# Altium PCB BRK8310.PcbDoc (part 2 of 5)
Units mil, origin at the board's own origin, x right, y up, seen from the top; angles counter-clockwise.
Board outline 6600.39 x 4492.13 mil, 4 copper layers (L1-Top, L2-GND, L3-GND, L4-BOT), stack 60.25 mil thick; 119 components, 266 nets, 1026 pads, 596 vias.
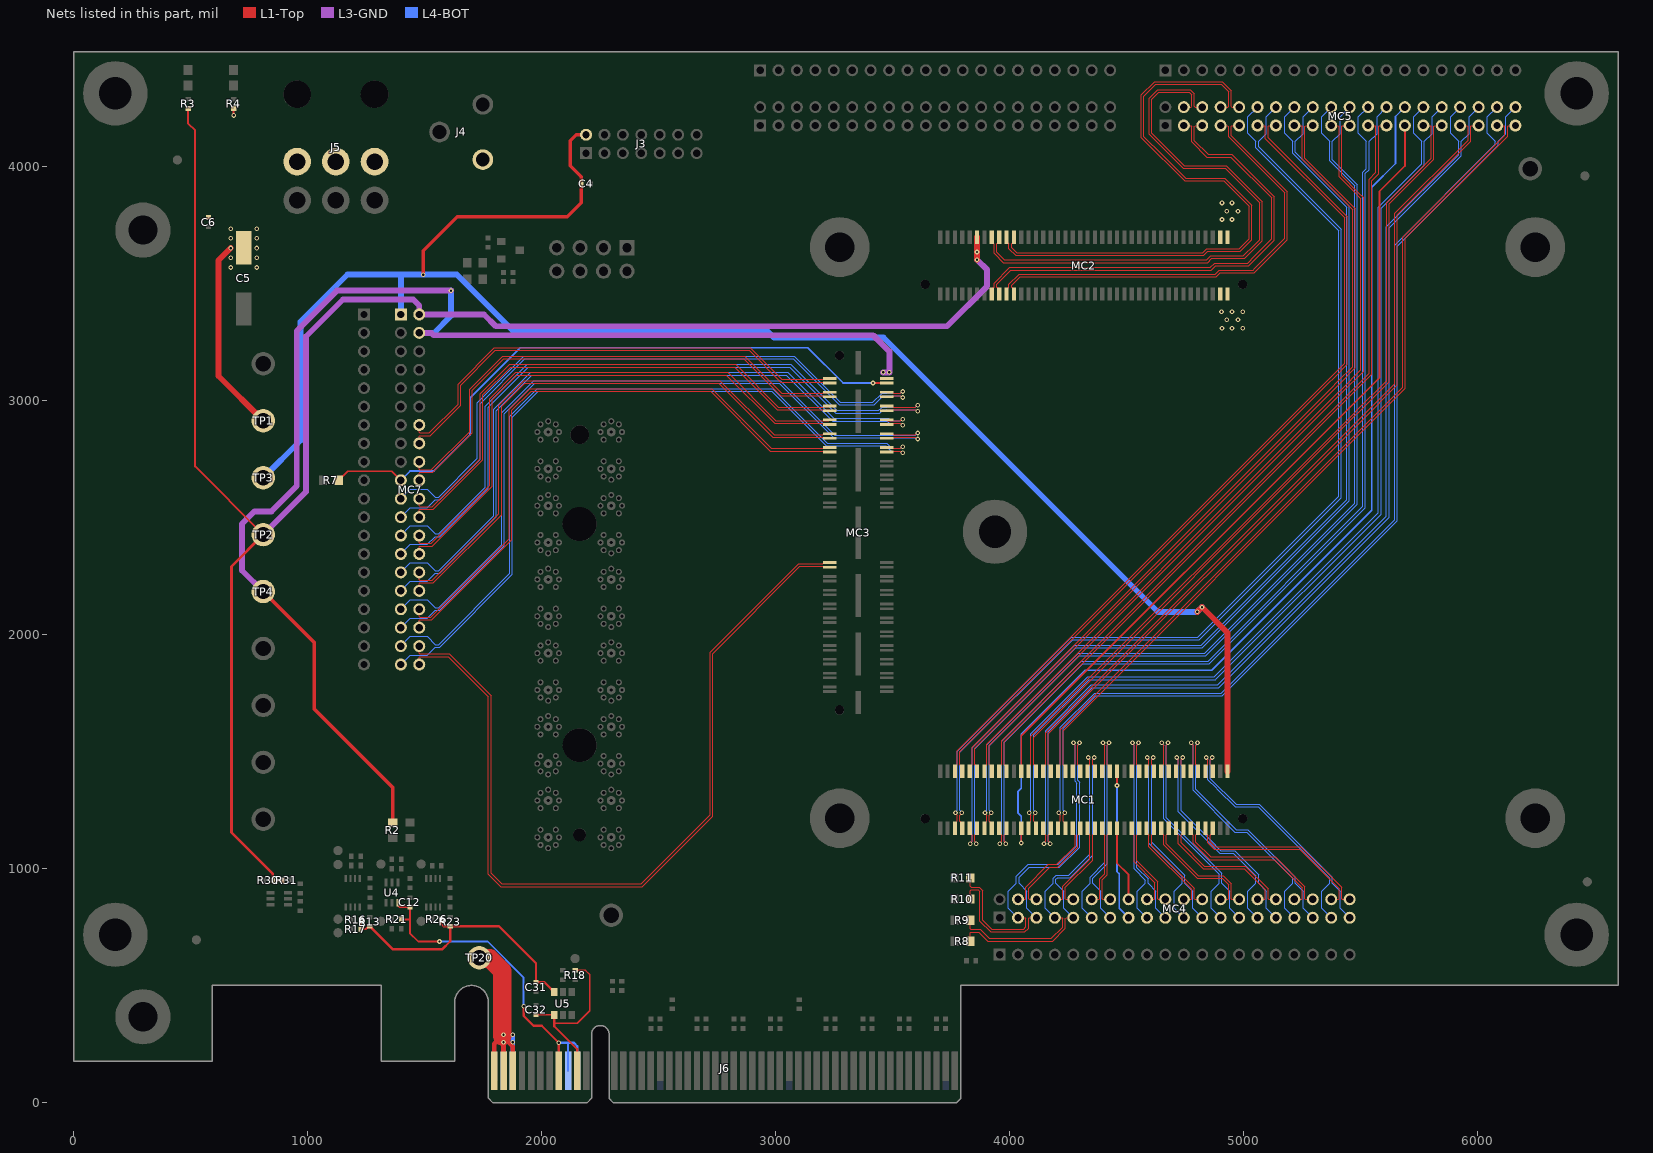
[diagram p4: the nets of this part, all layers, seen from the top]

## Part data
*: library part OKLOGO, partnumber=ALIGNI_IGNORE
C1 C3 C4: library part 000070, "Ceramic capacitor", Manufacturer=Kemet, Tolerance (%)=10, ValueFloat=1E-7
C2: library part 001983, "Ceramic capacitor", Manufacturer=Murata, Tolerance (%)=20, ValueFloat=1E-5
C5: library part 001532, "Polarized", Manufacturer=Panasonic, ValueFloat=0.00022, Voltage=25V, x_tolerance=20, x_voltage-rating=25
C6: library part 001073, "Ceramic capacitor", Manufacturer="Taiyo Yuden", Tolerance (%)=10, ValueFloat=1E-7, Voltage=25V
C7 C8 C9 C10 C11 C12 C13 C14 C15 C16 C17 C18 C19 C20 C21 C22 C23 C24 C25 C26 C27 C28 C29 C30 C31 C32: library part 001073, Manufacturer=Kemet, partnumber=000070, ValueFloat=1E-7, x_tolerance=10
D1 D2: library part 001433, "LED", Manufacturer=Dialight, Manufacturer_PN=598-8070-107F
FID1 FID2 FID3 FID4: "PCB fiducial"
J1: Package=None
J2: library part 001193, Manufacturer="Sullins Electronics Corp."
J3: library part 000541, "2mm header, shrouded", Manufacturer=Molex
J4: library part 000356, "DC power connector - high current", Manufacturer="CUI Inc."
J5: library part 001950, Manufacturer=Molex
J6: library part PCIEX8
MC1 MC2: library part 000059, "0.8mm high-density header", Manufacturer=Samtec
MC3: library part 002313, "0.5mm hi-speed, high-density header (female)", Manufacturer=Samtec
MC4 MC5 MC6 MC7: library part 000583, Manufacturer=Molex
MC8 MC9 MC10 MC11: library part 001334, Manufacturer=3M, Manufacturer_PN=951120-8622-AR
MH1 MH2 MH3 MH4: "Mounting hole"
Q1: library part 002018, Manufacturer=Vishay
R1 R2 R5 R6 R7 R8 R9 R10 R11: library part 000411, "Zero-ohm resistor", Manufacturer=Vishay, ValueFloat=0
R3: library part 001038, "Thick-film resistor", Manufacturer=Vishay, Tolerance (%)=1, ValueFloat=549
R4: library part 001162, "Thick-film resistor", Manufacturer=Vishay, Tolerance (%)=1, ValueFloat=2000
R12 R16 R17 R20 R21 R22 R26: library part Resistor-NoLoad, "Resistor, NoLoad", partnumber=ALIGNI_IGNORE
R13 R23: library part 000964, Manufacturer=Vishay, ValueFloat=200000, x_tolerance=1
R14 R15 R30 R31: library part 001008, Manufacturer=Vishay, ValueFloat=4750, x_tolerance=1
R18 R24 R25 R32 R33: library part 001070, "Thick-film resistor", Manufacturer=Vishay, Tolerance (%)=1, ValueFloat=100000
R27 R28 R29: library part 000755, Manufacturer=Vishay, ValueFloat=0, x_tolerance=1
TP1 TP2 TP3 TP4 TP5 TP6 TP7 TP8 TP17 TP18 TP19 TP20: library part TP-PTH-65/100, "Test point, plated through-hole, 65/100mil"
TP9 TP10 TP11 TP12 TP13 TP14 TP15 TP16 TP21: library part TESTPOINT-SMD40, "Test point, surface-mount, 40mil"
U1: library part 000728, "1.25V Voltage Reference", Manufacturer="Texas Instruments"
U2 U6: library part 001474, Manufacturer="Texas Instruments"
U4: library part 002140, "Level Translator, 0.65V - 3.6V, Direction Control", Manufacturer="Texas Instruments"
U5: library part 002224, "Load Switch with Adjustable Current Limit, Latching", Manufacturer="Diodes Incorporated"

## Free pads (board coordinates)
  round 236.22 hole 125.2: 0(295.27,368.11) 0(295.27,3730.31)
  round 275.59 hole 137.8: MH(177.17,718.5) MH(177.17,4314.96) MH(3937.01,2440.94) MH(6423.22,718.5) MH(6423.23,4314.96)

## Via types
v1: diameter 20, hole 10, L1-Top to L4-BOT, tented both sides, 596 vias

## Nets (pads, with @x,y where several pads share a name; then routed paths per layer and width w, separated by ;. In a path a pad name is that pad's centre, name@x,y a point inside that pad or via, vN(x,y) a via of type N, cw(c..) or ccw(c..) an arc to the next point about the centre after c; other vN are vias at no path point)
+1.2V_DDR: MC3.80 MC7.4 R2.2 TP4.1 | length 5669
  L1-Top w16: TP4.1@809.29,2185.43 1027.56,1967.16 1027.56,1683.59 1363.39,1347.76 R2.2@1363.39,1198.78
  L3-GND w25: TP4.1@809.29,2185.43 718.88,2275.84 718.88,2474.79 772.22,2528.12 844.46,2528.12 952.76,2636.42 952.76,3299.21 1125.12,3471.58 v1(1612.15,3471.58) ; MC7.4@1476.37,3290.86 1527.89,3290.86 1538.03,3280.72 3416.06,3280.72 3485.62,3211.17 v1(3485.62,3122.05) v1(3458.93,3122.05)
  L4-BOT w25: MC7.4@1476.37,3290.86 1538.89,3290.86 1612.15,3364.12 v1(1612.15,3471.58)
+1.8V: C4.1 J3.2 MC1.2 MC7.1 TP3.1 | length 7445.3
  L1-Top w15: v1(1493.22,3540.1) 1493.22,3641.64 1638.98,3787.4 2108.54,3787.4 2169.04,3847.9 C4.1@2169.04,3927.72 2169.04,3958.48 2122.05,4005.47 2122.05,4111.84 2148,4137.79 J3.2@2189.12,4137.79
  L1-Top w25: v1(4801.52,2098.74) v1(4821.74,2118.94) ; v1(4821.74,2118.94) 4931.09,2009.59 MC1.2@4931.09,1416.73
  L4-BOT w25: TP3.1@809.29,2672.2 968.5,2831.41 968.5,3338.58 1170.02,3540.1 1397.63,3540.1 ; MC7.1@1397.63,3369.6 1397.63,3540.1 ; v1@4821.73,2118.95 v1(4801.52,2098.74) 4801.18,2098.4 4633.88,2098.4 3460.62,3271.65 2991.73,3271.65 2960.23,3303.15 1873.68,3303.15 1636.74,3540.1 v1(1493.22,3540.1) 1397.63,3540.1
+3.3V: MC2.70 MC7.2 R3.2 R30.2 R31.2 TP2.1 | length 7900.4
  L1-Top w8: R3.2@488.36,4250 488.36,4185.57 517.89,4156.04 517.89,2720.22 TP2.1@809.29,2428.82
  L1-Top w12: TP2.1@809.29,2428.82 673.23,2292.75 673.23,1156.12 850.44,978.91 R30.2@850.44,951.56 R31.2@889.81,951.56
  L1-Top w25: v1(3860.23,3604.12) v1(3860.23,3636.94) MC2.70@3860.23,3700.2
  L3-GND w25: TP2.1@809.29,2428.82 992.13,2611.65 992.13,3275.28 1150.23,3433.38 1450.5,3433.38 1476.19,3407.69 1476.19,3369.78 MC7.2@1476.37,3369.6 1753.32,3369.6 1803.66,3319.27 3732.18,3319.27 3903.54,3490.63 3903.54,3560.81 v1(3860.23,3604.12) v1(3860.23,3636.94)
+3.3V_PCIE_C: C12.2 J6.A9 J6.A10 J6.B8 R21.2 U4.6 | length 1567.9
  L1-Top w8: U4.6@1384.98,855.1 1384.98,845.26 1393.64,836.59 C12.2@1436.16,836.59 1436.16,784.23 ; R21.2@1398.76,784.23 1436.16,784.23 ; v1(1563.13,689.7) 1471.85,689.7 1436.16,725.39 1436.16,784.23
  L1-Top w10: v1(1922.6,413.07) 1922.6,371.12 1964.31,329.42 2000,329.42 v1(2072.83,256.59) J6.B8@2072.83,137.79
  L4-BOT w8: v1(1563.13,689.7) 1768.46,689.7 1922.6,535.56 v1(1922.6,413.07)
  L4-BOT w10: v1(2072.83,256.59) 2114.17,256.59 ; J6.A9@2112.2,137.79 2112.2,254.61 2114.17,256.59 ; J6.A10@2151.57,137.79 2151.57,242.13 2137.11,256.59 2114.17,256.59
+3.3VAUX_PCIE: C31.2 R13.2 R16.2 R17.2 R23.2 R26.2 U5.6 | length 1217.9
  L1-Top w10: R17.2@1225.53,742.89 1247.93,742.89 1254.9,749.86 1260.06,749.86 R13.2@1264.9,754.71 1266.87,754.71 1271.72,749.86 1271.72,747.89 1363.57,656.04 1573.76,656.04 1608.41,690.69 R23.2@1608.41,754.71 ; R17.2@1225.53,744.86 R16.2@1225.53,782.26 ; R26.2@1571.01,784.23 1571.01,764.34 1580.64,754.71 R23.2@1608.41,754.71 ; U5.6@2053.14,473.62 2053.14,477.56 2044.36,486.34 2040.43,486.34 2011.53,515.24 C31.2@1975.47,515.24 1975.47,596.44 1817.2,754.71 R23.2@1608.41,754.71
+3.3VAUX_PCIE_C: C32.2 J6.B10 R18.2 U5.1 | length 754.3
  L1-Top w7: 2053.14,339.98 2150.99,339.98 2204.34,393.33 2204.34,548.63 2186.83,566.14 R18.2@2142.43,566.14
  L1-Top w8: C32.2@1975.47,376.92 2051.42,376.92 U5.1@2053.14,375.2
  L1-Top w10: U5.1@2053.14,375.2 2053.14,339.98 2053.14,327.85 2151.57,229.43 J6.B10@2151.57,137.79
+12V_PCIE_C: J6.A2 J6.A3 J6.B1 J6.B2 J6.B3 TP20.1 | length 1178.2
  L1-Top w20: J6.B1@1797.24,137.79 1797.24,252.07 1831.02,285.86 1836.61,280.27 ; J6.B2@1836.61,137.79 v1(1836.61,258.56) 1836.61,280.27 ; J6.B3@1875.98,137.79 1875.98,240.9 1836.61,280.27
  L1-Top w80: TP20.1@1732.73,620.68 1736.56,616.85 1777.99,616.85 1831.02,563.82 v1@1831.02,285.86
  L4-BOT w20: J6.A2@1836.61,137.79 v1(1836.61,258.56) v1(1836.61,291.39) ; J6.A3@1875.98,137.79 v1(1875.98,258.56) v1(1875.98,291.39)
+VDCIN: C5.1 C6.2 J4.1 J5.1 J5.2 J5.3 MC2.1 MC2.2 MC2.3 MC2.4 R4.2 TP1.1 | length 868
  L1-Top w8: v1(682.87,4220.43) R4.2@682.87,4250
  L1-Top w25: v1(670.87,3653.38) 618.54,3601.04 618.54,3106.34 TP1.1@809.29,2915.59
  other v1: 4907.47,3311.02 4950.1,3311.02 4995.46,3311.02 4927.16,3346.46 4975.39,3346.46 4904.74,3381.89 4950.1,3381.89 4995.46,3381.89 670.87,3570.32 781.47,3570.32 670.87,3611.85 781.47,3611.85 781.47,3653.38 670.87,3694.91 781.47,3694.91 670.87,3736.44 781.47,3736.44 4907.47,3775.59 4950.1,3775.59 4927.16,3811.02 4975.39,3811.02 4907.47,3846.46 4950.1,3846.46
B64_L1N: MC1.12 MC4.33 | length 1118.7
  L1-Top w5.25: MC1.12@4773.61,1416.73 4773.61,1436.22 4780.04,1442.65 4780.66,1442.65 4783.74,1445.73 4783.74,1528.92 4776.36,1536.29 v1(4776.36,1539.37)
  L4-BOT w5.25: v1(4776.36,1539.37) 4776.36,1536.29 4783.74,1528.92 4783.74,1335.29 4962.76,1156.27 5013.33,1156.27 5209.75,959.85 5209.75,938.11 5175.43,903.78 5175.43,832.44 MC4.33@5216.53,791.34
B64_L1P: MC1.10 MC4.35 | length 1118.2
  L1-Top w5.25: v1(4802.36,1539.37) 4802.36,1536.29 4794.99,1528.92 4794.99,1445.73 4798.06,1442.65 4798.68,1442.65 4805.11,1436.22 MC1.10@4805.11,1416.73
  L4-BOT w5.25: v1(4802.36,1539.37) 4802.36,1536.29 4794.99,1528.92 4794.99,1339.95 4967.42,1167.52 5017.99,1167.52 5221,964.51 5221,938.05 5254.73,904.32 5254.73,831.88 MC4.35@5295.27,791.34
B64_L2N: MC1.16 MC4.29 | length 938.9
  L1-Top w5.25: MC1.16@4710.62,1436.22 4717.05,1442.65 4717.67,1442.65 4720.74,1445.73 4720.74,1452.75 4720.74,1465.93 4713.37,1473.3 v1(4713.37,1476.38)
  L4-BOT w5.25: v1(4713.37,1476.38) 4713.37,1473.3 4720.74,1465.93 4720.74,1464.57 4720.74,1243.66 4838.42,1125.98 4897.45,1066.95 4956.3,1066.95 5052.27,970.98 5052.27,938.11 5017.95,903.78 5017.95,832.44 MC4.29@5059.05,791.34
B64_L2P: MC1.14 MC4.31 | length 957.9
  L1-Top w5.25: v1(4739.37,1476.38) 4739.37,1473.3 4731.99,1465.93 4731.99,1457.41 4731.99,1445.73 4735.07,1442.65 4735.69,1442.65 4742.12,1436.22 MC1.14@4742.12,1416.73
  L4-BOT w5.25: v1(4739.37,1476.38) 4739.37,1473.3 4731.99,1465.93 4731.99,1464.57 4731.99,1248.32 4854.33,1125.98 4902.11,1078.2 4960.96,1078.2 5063.52,975.64 5063.52,938.05 5097.25,904.32 5097.25,831.88 MC4.31@5137.79,791.34
B64_L3N: MC1.15 MC4.30 | length 596.9
  L1-Top w5.25: MC1.15@4710.62,1173.82 4710.62,1154.33 4717.05,1147.9 4717.67,1147.9 4720.74,1144.82 4720.74,1107.62 4827.49,1000.87 5002.52,1000.87 5092.79,910.6 5092.79,873.15 5089.72,870.08 MC4.30@5059.05,870.08
B64_L3P: MC1.13 MC4.32 | length 596.9
  L1-Top w5.25: MC1.13@4742.12,1173.82 4742.12,1154.33 4735.69,1147.9 4735.07,1147.9 4731.99,1144.82 4731.99,1112.28 4832.15,1012.12 5007.18,1012.12 5104.04,915.26 5104.04,873.15 5107.12,870.08 MC4.32@5137.79,870.08
B64_L4N: MC1.8 MC4.37 | length 1060.1
  L1-Top w5.25: MC1.8@4836.61,1416.73 4836.61,1436.22 4843.04,1442.65 4843.65,1442.65 4846.73,1445.73 4846.73,1452.75 4846.73,1465.93 4839.35,1473.3 v1(4839.35,1476.38)
  L4-BOT w5.25: v1(4839.35,1476.38) 4839.35,1473.3 4846.73,1465.93 4846.73,1381.45 4879.83,1348.34 4887.79,1340.39 4963.57,1264.6 5062.43,1264.6 5367.23,959.8 5367.23,938.11 5332.91,903.78 5332.91,832.44 MC4.37@5374.01,791.34
B64_L4P: MC1.6 MC4.39 | length 1059.6
  L1-Top w5.25: v1(4865.35,1476.38) 4865.35,1473.3 4857.98,1465.93 4857.98,1457.41 4857.98,1445.73 4861.05,1442.65 4861.67,1442.65 4868.1,1436.22 MC1.6@4868.1,1416.73
  L4-BOT w5.25: v1(4865.35,1476.38) 4865.35,1473.3 4857.98,1465.93 4857.98,1386.11 4968.23,1275.85 5067.09,1275.85 5378.48,964.46 5378.48,938.05 5412.21,904.32 5412.21,831.88 MC4.39@5452.75,791.34
B64_L5N: MC1.7 MC4.38 | length 787.1
  L1-Top w5.25: MC1.7@4836.61,1173.82 4836.61,1154.33 4843.04,1147.9 4843.65,1147.9 4846.73,1144.82 4846.73,1110.9 4873.5,1084.12 5239.6,1084.12 5407.75,915.97 5407.75,873.15 5404.68,870.08 MC4.38@5374.01,870.08
B64_L5P: MC1.5 MC4.40 | length 787.1
  L1-Top w5.25: MC1.5@4868.1,1173.82 4868.1,1154.33 4861.67,1147.9 4861.05,1147.9 4857.98,1144.82 4857.98,1115.56 4878.16,1095.37 5244.26,1095.37 5419,920.63 5419,873.15 5422.08,870.08 MC4.40@5452.75,870.08
B64_L6N: MC1.11 MC4.34 | length 695
  L1-Top w5.25: MC1.11@4773.61,1173.82 4773.61,1154.33 4780.04,1147.9 4780.66,1147.9 4783.74,1144.82 4783.74,1110.05 4853.86,1039.93 5129.58,1039.93 5250.27,919.23 5250.27,873.15 5247.2,870.08 MC4.34@5216.53,870.08
B64_L6P: MC1.9 MC4.36 | length 695
  L1-Top w5.25: MC1.9@4805.11,1173.82 4805.11,1154.33 4798.68,1147.9 4798.06,1147.9 4794.99,1144.82 4794.99,1114.71 4858.52,1051.18 5134.24,1051.18 5261.52,923.89 5261.52,873.15 5264.6,870.08 MC4.36@5295.27,870.08
B64_L7N: MC1.23 MC4.22 | length 416.1
  L1-Top w5.25: MC1.23@4584.64,1173.82 4584.64,1154.33 4591.07,1147.9 4591.69,1147.9 4594.76,1144.82 4594.76,1095.19 4777.83,912.12 4777.83,873.15 4774.76,870.08 MC4.22@4744.09,870.08
B64_L7P: MC1.21 MC4.24 | length 416.1
  L1-Top w5.25: MC1.21@4616.13,1173.82 4616.13,1154.33 4609.7,1147.9 4609.09,1147.9 4606.01,1144.82 4606.01,1099.85 4789.08,916.78 4789.08,873.15 4792.16,870.08 MC4.24@4822.83,870.08
B64_L8N: MC1.20 MC4.25 | length 1010.8
  L1-Top w5.25: MC1.20@4647.63,1416.73 4647.63,1436.22 4654.06,1442.65 4654.68,1442.65 4657.75,1445.73 4657.75,1468.07 4657.75,1528.92 4650.38,1536.29 v1(4650.38,1539.37)
  L4-BOT w5.25: v1(4650.38,1539.37) 4650.38,1536.29 4657.75,1528.92 4657.75,1214.12 4894.79,977.09 4894.79,938.11 4860.47,903.78 4860.47,832.44 MC4.25@4901.57,791.34
B64_L8P: MC1.18 MC4.27 | length 1010.3
  L1-Top w5.25: v1(4676.38,1539.37) 4676.38,1536.29 4669,1528.92 4669,1472.73 4669,1445.73 4672.08,1442.65 4672.7,1442.65 4679.13,1436.22 MC1.18@4679.13,1416.73
  L4-BOT w5.25: v1(4676.38,1539.37) 4676.38,1536.29 4669,1528.92 4669,1218.78 4906.04,981.74 4906.04,938.05 4939.77,904.32 4939.77,831.88 MC4.27@4980.31,791.34
B64_L9N: MC1.24 MC4.21 | length 845.6
  L1-Top w5.25: MC1.24@4584.64,1416.73 4584.64,1436.22 4591.07,1442.65 4591.69,1442.65 4594.76,1445.73 4594.76,1452.75 4594.76,1465.93 4587.39,1473.3 v1(4587.39,1476.38)
  L4-BOT w5.25: v1(4587.39,1476.38) 4587.39,1473.3 4594.76,1465.93 4594.76,1109.76 4737.31,967.21 4737.31,938.11 4702.99,903.78 4702.99,832.44 MC4.21@4744.09,791.34
B64_L9P: MC1.22 MC4.23 | length 845.2
  L1-Top w5.25: v1(4613.39,1476.38) 4613.39,1473.3 4606.01,1465.93 4606.01,1457.41 4606.01,1445.73 4609.09,1442.65 4609.7,1442.65 4616.13,1436.22 MC1.22@4616.13,1416.73
  L4-BOT w5.25: v1(4613.39,1476.38) 4613.39,1473.3 4606.01,1465.93 4606.01,1114.42 4748.56,971.87 4748.56,938.05 4782.29,904.32 4782.29,831.88 MC4.23@4822.83,791.34
B64_L10N: MC1.28 MC4.17 | length 932.5
  L1-Top w5.25: MC1.28@4521.65,1416.73 4521.65,1436.22 4528.08,1442.65 4528.69,1442.65 4531.77,1445.73 4531.77,1528.92 4524.39,1536.29 v1(4524.39,1539.37)
  L4-BOT w5.25: v1(4524.39,1539.37) 4524.39,1536.29 4531.77,1528.92 4531.77,1000.35 4579.83,952.28 4579.83,938.11 4545.51,903.78 4545.51,832.44 MC4.17@4586.61,791.34
B64_L10P: MC1.26 MC4.19 | length 932
  L1-Top w5.25: v1(4550.39,1539.37) 4550.39,1536.29 4543.02,1528.92 4543.02,1445.73 4546.09,1442.65 4546.71,1442.65 4553.14,1436.22 MC1.26@4553.14,1416.73
  L4-BOT w5.25: v1(4550.39,1539.37) 4550.39,1536.29 4543.02,1528.92 4543.02,1005.01 4591.08,956.94 4591.08,938.05 4624.81,904.32 4624.81,831.88 MC4.19@4665.35,791.34
B64_L11N_GC: MC1.39 MC4.8 | length 388.3
  L1-Top w5.25: MC4.8@4192.91,870.08 4223.58,870.08 4226.65,873.15 4226.65,925.66 4245.86,944.86 4342.79,1041.8 4342.79,1144.82 4339.72,1147.9 4339.1,1147.9 4332.67,1154.33 MC1.39@4332.67,1173.82
B64_L11P_GC: MC1.37 MC4.10 | length 388.3
  L1-Top w5.25: MC4.10@4271.65,870.08 4240.98,870.08 4237.9,873.15 4237.9,921 4354.04,1037.14 4354.04,1144.82 4357.12,1147.9 4357.74,1147.9 4364.17,1154.33 MC1.37@4364.17,1173.82
B64_L12N_GC: MC1.43 MC4.4 | length 448.4
  L1-Top w5.25: MC4.4@4035.43,870.08 4066.09,870.08 4069.17,873.15 4069.17,922.62 4165.4,1018.84 4201.09,1018.84 4279.8,1097.56 4279.8,1144.82 4276.72,1147.9 4276.11,1147.9 4269.68,1154.33 MC1.43@4269.68,1173.82
B64_L12P_GC: MC1.41 MC4.6 | length 448.4
  L1-Top w5.25: MC4.6@4114.17,870.08 4083.5,870.08 4080.42,873.15 4080.42,917.96 4170.06,1007.59 4205.75,1007.59 4291.05,1092.9 4291.05,1144.82 4294.13,1147.9 4294.74,1147.9 4301.17,1154.33 MC1.41@4301.17,1173.82
B64_L13N_GC: MC1.27 MC4.18 | length 376.9
  L1-Top w5.25: MC1.27@4521.65,1173.82 4521.65,1154.33 4528.08,1147.9 4528.69,1147.9 4531.77,1144.82 4531.77,1029.74 4620.35,941.15 4620.35,873.15 4617.28,870.08 MC4.18@4586.61,870.08
B64_L13P_GC: MC1.25 MC4.20 | length 376.9
  L1-Top w5.25: MC1.25@4553.14,1173.82 4553.14,1154.33 4546.71,1147.9 4546.09,1147.9 4543.02,1144.82 4543.02,1034.4 4631.6,945.81 4631.6,873.15 4634.68,870.08 MC4.20@4665.35,870.08
B64_L14N_GC: MC1.47 MC5.38 | length 4210.9
  L1-Top w5.25: MC1.47@4206.69,1173.82 4206.69,1193.31 4213.12,1199.74 4213.73,1199.74 4216.81,1202.81 4216.81,1229.68 4209.43,1237.05 v1(4209.43,1240.16)
  L4-BOT w5.25: v1(4209.43,1240.16) 4209.43,1243.23 4216.81,1250.61 4216.81,1605.62 4362.9,1751.71 4903.72,1751.71 5644.73,2492.72 5644.73,3666.07 6075.89,4097.24 6075.89,4109.14 6041.57,4143.46 6041.57,4214.8 MC5.38@6082.67,4255.9
B64_L14P_GC: MC1.45 MC5.40 | length 4210.4
  L1-Top w5.25: v1(4235.43,1240.16) 4235.43,1237.05 4228.06,1229.68 4228.06,1202.81 4231.13,1199.74 4231.75,1199.74 4238.18,1193.31 MC1.45@4238.18,1173.82
  L4-BOT w5.25: v1(4235.43,1240.16) 4235.43,1243.23 4228.06,1250.61 4228.06,1600.96 4367.56,1740.46 4908.38,1740.46 5655.98,2488.06 5655.98,3661.41 6087.14,4092.58 6087.14,4109.19 6120.87,4142.92 6120.87,4215.36 MC5.40@6161.41,4255.9
B64_L15N: MC1.35 MC4.12 | length 349.2
  L1-Top w5.25: MC4.12@4350.39,870.08 4381.06,870.08 4384.13,873.15 4384.13,957.44 4405.78,979.1 4405.78,1144.82 4402.71,1147.9 4402.09,1147.9 4395.66,1154.33 MC1.35@4395.66,1173.82
B64_L15P: MC1.33 MC4.14 | length 349.2
  L1-Top w5.25: MC1.33@4427.16,1173.82 4427.16,1154.33 4420.73,1147.9 4420.11,1147.9 4417.03,1144.82 4417.03,974.44 4395.38,952.78 4395.38,873.15 4398.46,870.08 MC4.14@4429.13,870.08
B64_L16N: MC1.51 MC5.34 | length 4304.4
  L1-Top w5.25: MC1.51@4143.69,1173.82 4143.69,1154.33 4150.12,1147.9 4150.74,1147.9 4153.82,1144.82 4153.82,1117.96 4146.44,1110.58 v1(4146.44,1107.48)
  L4-BOT w5.25: v1(4146.44,1107.48) 4146.44,1110.56 4153.82,1117.93 4153.82,1591.41 4348.61,1786.21 4889.43,1786.21 5610.23,2507.01 5610.23,3744.09 5918.41,4052.28 5918.41,4109.14 5884.09,4143.46 5884.09,4214.8 MC5.34@5925.19,4255.9
B64_L16P: MC1.49 MC5.36 | length 4303.9
  L1-Top w5.25: v1(4172.44,1107.48) 4172.44,1110.58 4165.07,1117.96 4165.07,1144.82 4168.14,1147.9 4168.76,1147.9 4175.19,1154.33 MC1.49@4175.19,1173.82
  L4-BOT w5.25: v1(4172.44,1107.48) 4172.44,1110.56 4165.07,1117.93 4165.07,1586.75 4353.27,1774.96 4894.09,1774.96 4897.38,1778.25 4944.24,1825.11 5614.89,2495.76 5621.48,2502.35 5621.48,3739.43 5929.66,4047.62 5929.66,4109.19 5963.39,4142.92 5963.39,4215.36 MC5.36@6003.93,4255.9
B64_L17N: MC1.44 MC4.3 R11.2 | length 1596.8
  L1-Top w5.25: R11.2@3831.19,961.18 3831.19,925.65 3835.16,921.67 3849.35,921.67 3869.27,921.67 3883.73,907.22 3883.73,781.47 3923.07,742.12 4059.33,742.12 4069.17,751.97 4069.17,788.26 4066.09,791.34 MC4.3@4035.43,791.34 ; MC1.44@4269.68,1416.73 4269.68,1436.22 4276.11,1442.65 4276.72,1442.65 4279.8,1445.73 4279.8,1468.07 4279.8,1528.92 4272.43,1536.29 v1(4272.43,1539.37)
  L4-BOT w5.25: MC4.3@4035.43,791.34 3994.33,832.44 3994.33,903.78 4028.65,938.11 4028.65,968.47 4079.03,1018.84 4207.95,1018.84 4287.18,1098.07 4287.18,1366.73 4279.8,1374.1 4279.8,1528.92 4272.43,1536.29 v1(4272.43,1539.37)
B64_L17P: MC1.42 MC4.5 R10.2 | length 1615
  L1-Top w5.25: R10.2@3831.19,870.92 3831.19,906.45 3835.16,910.42 3842.26,910.42 3864.61,910.42 3872.48,902.56 3872.48,776.81 3918.41,730.88 4063.99,730.88 4080.42,747.31 4080.42,788.26 4083.5,791.34 MC4.5@4114.17,791.34 ; v1(4298.43,1539.37) 4298.43,1536.29 4291.05,1528.92 4291.05,1472.73 4291.05,1445.73 4294.13,1442.65 4294.74,1442.65 4301.17,1436.22 MC1.42@4301.17,1416.73
  L4-BOT w5.25: MC4.5@4114.17,791.34 4073.63,831.88 4073.63,904.32 4039.9,938.05 4039.9,963.81 4083.69,1007.59 4212.61,1007.59 4298.43,1093.41 4298.43,1371.39 4291.05,1378.76 4291.05,1528.92 4298.43,1536.29 v1(4298.43,1539.37)
B64_L18N: MC1.56 MC5.29 | length 3505.5
  L1-Top w5.25: MC1.56@4080.7,1416.73 4080.7,1436.22 4087.13,1442.65 4087.75,1442.65 4090.82,1445.73 4090.82,1567.21 5474.05,2950.44 5482.01,2958.39 5610.79,3087.17 5610.79,3847.26 5801.45,4037.92 5801.45,4174.09 5798.38,4177.16 MC5.29@5767.71,4177.16
B64_L18P: MC1.54 MC5.31 | length 3505.5
  L1-Top w5.25: MC1.54@4112.2,1416.73 4112.2,1436.22 4105.77,1442.65 4105.15,1442.65 4102.07,1445.73 4102.07,1562.55 5482.01,2942.48 5486.67,2947.14 5622.04,3082.51 5622.04,3842.6 5812.7,4033.26 5812.7,4174.09 5815.78,4177.16 MC5.31@5846.45,4177.16
B64_L19N: MC1.19 MC4.26 | length 517.9
  L1-Top w5.25: MC1.19@4647.63,1173.82 4647.63,1154.33 4654.06,1147.9 4654.68,1147.9 4657.75,1144.82 4657.75,1102.64 4801.38,959.01 4908.35,959.01 4935.11,932.25 4935.11,899.99 4935.31,899.79 4935.31,873.15 4932.24,870.08 MC4.26@4901.57,870.08
B64_L19P: MC1.17 MC4.28 | length 517.9
  L1-Top w5.25: MC1.17@4679.13,1173.82 4679.13,1154.33 4672.7,1147.9 4672.08,1147.9 4669,1144.82 4669,1107.3 4806.04,970.26 4913.01,970.26 4946.36,936.91 4946.36,904.65 4946.56,904.45 4946.56,873.15 4949.64,870.08 MC4.28@4980.31,870.08
B64_L20N: MC1.40 MC4.7 R9.2 | length 1404.4
  L1-Top w5.25: R9.2@3830.99,780.66 3830.99,744.23 3834.06,741.16 3873.28,741.16 3911.43,703.01 4178.18,703.01 4226.65,751.47 4226.65,788.26 4223.58,791.34 MC4.7@4192.91,791.34 ; MC1.40@4332.67,1436.22 4339.1,1442.65 4339.72,1442.65 4342.79,1445.73 4342.79,1452.75 4342.79,1465.93 4335.42,1473.3 v1(4335.42,1476.38)
  L4-BOT w5.25: MC4.7@4192.91,791.34 4151.81,832.44 4151.81,903.78 4186.13,938.11 4186.13,959.95 4199.61,973.44 4253.06,973.44 4342.79,1063.18 4342.79,1465.93 4335.42,1473.3 v1(4335.42,1476.38)
B64_L20P: MC1.38 MC4.9 R8.2 | length 1442
  L1-Top w5.25: R8.2@3830.99,690.4 3830.99,726.83 3834.06,729.91 3868.62,729.91 3906.77,691.76 4182.84,691.76 4237.9,746.81 4237.9,788.26 4240.98,791.34 MC4.9@4271.65,791.34 ; v1(4361.42,1476.38) 4361.42,1473.3 4354.04,1465.93 4354.04,1457.41 4354.04,1445.73 4357.12,1442.65 4357.74,1442.65 4364.17,1436.22 MC1.38@4364.17,1416.73
  L4-BOT w5.25: MC4.9@4271.65,791.34 4231.11,831.88 4231.11,904.32 4197.38,938.05 4197.38,955.29 4204.27,962.19 4257.72,962.19 4354.04,1058.52 4354.04,1465.93 4361.42,1473.3 v1(4361.42,1476.38)
B64_L21N: MC1.36 MC4.11 | length 938.3
  L1-Top w5.25: MC1.36@4395.66,1416.73 4395.66,1436.22 4402.09,1442.65 4402.71,1442.65 4405.78,1445.73 4405.78,1468.07 4405.78,1528.92 4398.41,1536.29 v1(4398.41,1539.37)
  L4-BOT w5.25: MC4.11@4350.39,791.34 4309.29,832.44 4309.29,903.78 4343.61,938.11 4343.61,965.3 4405.78,1027.48 4405.78,1464.57 4405.78,1528.92 4398.41,1536.29 v1(4398.41,1539.37)
B64_L21P: MC1.34 MC4.13 | length 937.8
  L1-Top w5.25: v1(4424.41,1539.37) 4424.41,1536.29 4417.03,1528.92 4417.03,1472.73 4417.03,1445.73 4420.11,1442.65 4420.73,1442.65 4427.16,1436.22 MC1.34@4427.16,1416.73
  L4-BOT w5.25: v1(4424.41,1539.37) 4424.41,1536.29 4417.03,1528.92 4417.03,1022.82 4354.86,960.64 4354.86,938.05 4388.59,904.32 4388.59,831.88 MC4.13@4429.13,791.34
B64_L22N: MC1.52 MC5.33 | length 3544.6
  L1-Top w5.25: MC1.52@4143.69,1416.73 4143.69,1436.22 4150.12,1442.65 4150.74,1442.65 4153.82,1445.73 4153.82,1581.41 5498.45,2926.04 5501.74,2929.34 5645.29,3072.88 5645.29,3801.34 5958.93,4114.99 5958.93,4174.09 5955.86,4177.16 MC5.33@5925.19,4177.16
B64_L22P: MC1.50 MC5.35 | length 3544.6
  L1-Top w5.25: MC1.50@4175.19,1416.73 4175.19,1436.22 4168.76,1442.65 4168.14,1442.65 4165.07,1445.73 4165.07,1576.75 5506.4,2918.09 5656.54,3068.22 5656.54,3796.68 5970.18,4110.33 5970.18,4174.09 5973.26,4177.16 MC5.35@6003.93,4177.16
B64_L23N: MC1.55 MC5.30 | length 4132.6
  L1-Top w5.25: MC1.55@4080.7,1173.82 4080.7,1193.31 4087.13,1199.74 4087.75,1199.74 4090.82,1202.81 4090.82,1229.68 4083.45,1237.05 v1(4083.45,1240.16)
  L4-BOT w5.25: v1(4083.45,1240.16) 4083.45,1243.23 4090.82,1250.61 4090.82,1577.21 4334.32,1820.71 4875.13,1820.71 5575.73,2521.3 5575.73,3827.7 5760.93,4012.91 5760.93,4109.14 5726.61,4143.46 5726.61,4214.8 MC5.30@5767.71,4255.9
B64_L23P: MC1.53 MC5.32 | length 4132.1
  L1-Top w5.25: v1(4109.45,1240.16) 4109.45,1237.05 4102.07,1229.68 4102.07,1202.81 4105.15,1199.74 4105.77,1199.74 4112.2,1193.31 MC1.53@4112.2,1173.82
  L4-BOT w5.25: v1(4109.45,1240.16) 4109.45,1243.23 4102.07,1250.61 4102.07,1572.55 4338.98,1809.46 4879.79,1809.46 4883.09,1812.75 4929.95,1859.61 5580.39,2510.05 5586.98,2516.64 5586.98,3823.04 5772.18,4008.25 5772.18,4109.19 5805.91,4142.92 5805.91,4215.36 MC5.32@5846.45,4255.9
B64_L24N: MC1.48 MC5.37 | length 3583.8
  L1-Top w5.25: MC1.48@4206.69,1416.73 4206.69,1436.22 4213.12,1442.65 4213.73,1442.65 4216.81,1445.73 4216.81,1595.61 5522.84,2901.65 5526.14,2904.94 5679.79,3058.59 5679.79,3699.48 6116.41,4136.11 6116.41,4174.09 6113.34,4177.16 MC5.37@6082.67,4177.16
B64_L24P: MC1.46 MC5.39 | length 3564.3
  L1-Top w5.25: MC1.46@4238.18,1436.22 4231.75,1442.65 4231.13,1442.65 4228.06,1445.73 4228.06,1590.95 5530.8,2893.69 5691.04,3053.93 5691.04,3694.82 6127.66,4131.45 6127.66,4174.09 6130.74,4177.16 MC5.39@6161.41,4177.16
B64_T0U_N12: MC1.32 MC4.15 | length 645.8
  L1-Top w7.5: v1(4458.65,1356.3) MC1.32@4458.65,1416.73
  L4-BOT w7.5: v1(4458.65,1356.3) 4458.65,988.11 4468.16,978.6 4468.16,831.05 MC4.15@4507.87,791.34
B64_T1U_N12: MC1.31 MC4.16 | length 324.1
  L1-Top w7.5: MC1.31@4458.65,1173.82 4458.65,1024.5 4507.87,975.28 MC4.16@4507.87,870.08
B64_T2U_N12: MC1.57 MC5.28 | length 4216.4
  L1-Top w7.5: v1(4049.2,1110.58) MC1.57@4049.2,1173.82
  L4-BOT w7.5: v1(4049.2,1110.58) 4049.2,1125.98 4049.2,1225.4 4034.87,1239.74 4034.87,1330.15 4049.2,1344.49 4049.2,1464.57 4049.2,1575.2 4322.72,1848.71 4863.54,1848.71 5547.73,2532.9 5547.73,3913.87 5648.64,4014.79 5648.64,4215.58 MC5.28@5688.97,4255.9
B64_T3U_N12: MC1.58 MC5.27 | length 3439.6
  L1-Top w7.5: MC1.58@4049.2,1416.73 4049.2,1568.9 5452.4,2972.09 5580.17,3099.86 5580.17,3895.53 5688.97,4004.33 MC5.27@5688.97,4177.16
B67_L13N_GC: MC3.71 MC7.22 | length 2278
  L1-Top w5.25: MC7.22@1476.37,2582.2 1476.37,2551.53 1479.45,2548.46 1519.68,2548.46 1531.87,2548.46 1737.32,2753.91 1737.32,3031.55 1862.14,3156.37 2828.68,3156.37 3010.92,2974.13 3201.71,2974.13 3202.64,2975.06 3227.42,2975.06 MC3.71@3230.7,2978.35
B67_L13P_GC: MC3.69 MC7.24 | length 2278
  L1-Top w5.25: MC7.24@1476.37,2503.46 1476.37,2534.13 1479.45,2537.21 1519.68,2537.21 1536.53,2537.21 1748.57,2749.25 1748.57,3026.89 1866.8,3145.12 2824.02,3145.12 3006.26,2962.88 3201.71,2962.88 3202.64,2961.94 3227.42,2961.94 MC3.69@3230.7,2958.66
B67_L14N_GC: MC3.60 MC7.37 | length 3206.8
  L1-Top w5.25: MC3.60@3474.01,2801.18 3477.29,2797.9 3502.06,2797.9 3503,2796.96 3512.13,2796.96 3532.85,2796.96 3540.22,2804.34 v1(3543.3,2804.34)
  L4-BOT w5.25: MC7.37@1397.63,1952.28 1438.73,1993.38 1510.07,1993.38 1544.4,1959.06 1558.58,1959.06 1862.77,2263.24 1862.77,2818.42 1862.77,2935.29 1980.35,3052.87 2986.5,3052.87 3220.17,2819.2 3475.42,2819.2 3497.65,2796.96 3532.85,2796.96 3540.22,2804.34 v1(3543.3,2804.34)
B67_L14P_GC: MC3.58 MC7.39 | length 3206.3
  L1-Top w5.25: MC3.58@3474.01,2781.49 3477.29,2784.78 3502.06,2784.78 3503,2785.71 3516.79,2785.71 3532.85,2785.71 3540.22,2778.34 v1(3543.3,2778.34)
  L4-BOT w5.25: MC7.39@1397.63,1873.54 1438.17,1914.08 1510.62,1914.08 1544.34,1947.81 1563.24,1947.81 1874.02,2258.58 1874.02,2930.63 1985.01,3041.62 2981.84,3041.62 3215.51,2807.95 3470.76,2807.95 3492.99,2785.71 3532.85,2785.71 3540.22,2778.34 v1(3543.3,2778.34)
B67_L15N: MC3.59 MC7.34 | length 2622.9
  L1-Top w5.25: MC7.34@1476.37,2109.76 1476.37,2079.09 1479.45,2076.02 1519.68,2076.02 1526.01,2076.02 1860.72,2410.73 1860.72,2964.21 1949.38,3052.87 1954.04,3052.87 2725.86,3052.87 2981.77,2796.96 3201.71,2796.96 3202.64,2797.9 3227.42,2797.9 MC3.59@3230.7,2801.18
B67_L15P: MC3.57 MC7.36 | length 2622.9
  L1-Top w5.25: MC7.36@1476.37,2031.02 1476.37,2061.69 1479.45,2064.77 1519.68,2064.77 1530.66,2064.77 1871.97,2406.07 1871.97,2959.55 1954.04,3041.62 2721.2,3041.62 2977.11,2785.71 3201.71,2785.71 3202.64,2784.78 3227.42,2784.78 MC3.57@3230.7,2781.49
B67_L16N: MC3.68 MC7.29 | length 2957.2
  L1-Top w5.25: MC3.68@3474.01,2919.29 3477.29,2916.01 3502.06,2916.01 3503,2915.07 3512.13,2915.07 3532.85,2915.07 3540.22,2922.45 v1(3543.3,2922.45)
  L4-BOT w5.25: MC7.29@1397.63,2267.24 1438.73,2308.34 1510.07,2308.34 1544.4,2274.02 1558.58,2274.02 1793.77,2509.21 1793.77,2774.43 1793.77,2812.8 1793.77,2963.87 1951.77,3121.87 3050.53,3121.87 3247.2,2925.2 3480.16,2925.2 3490.28,2915.07 3532.85,2915.07 3540.22,2922.45 v1(3543.3,2922.45)
B67_L16P: MC3.66 MC7.31 | length 2956.8
  L1-Top w5.25: MC3.66@3474.01,2899.6 3477.29,2902.89 3502.06,2902.89 3503,2903.82 3516.79,2903.82 3532.85,2903.82 3540.22,2896.45 v1(3543.3,2896.45)
  L4-BOT w5.25: MC7.31@1397.63,2188.5 1438.17,2229.04 1510.62,2229.04 1544.34,2262.77 1563.24,2262.77 1805.02,2504.55 1805.02,2779.09 1805.02,2959.21 1956.43,3110.62 3045.87,3110.62 3242.54,2913.95 3475.5,2913.95 3485.62,2903.82 3532.85,2903.82 3540.22,2896.45 v1(3543.3,2896.45)
B67_L17N: MC3.64 MC7.33 | length 3209.4
  L1-Top w5.25: MC3.64@3474.01,2860.23 3477.29,2856.95 3502.06,2856.95 3503,2856.02 3595.84,2856.02 3603.22,2863.39 v1(3606.29,2863.39)
  L4-BOT w5.25: MC7.33@1397.63,2109.76 1438.73,2150.86 1510.07,2150.86 1544.4,2116.54 1558.58,2116.54 1828.27,2386.22 1828.27,2949.58 1966.06,3087.37 3019.31,3087.37 3252.35,2854.33 3595.84,2854.33 3604.9,2863.39 v1(3606.29,2863.39)
B67_L17P: MC3.62 MC7.35 | length 3207.5
  L1-Top w5.25: MC3.62@3474.01,2840.55 3477.29,2843.83 3502.06,2843.83 3503,2844.77 3595.84,2844.77 3603.22,2837.39 v1(3606.29,2837.39)
  L4-BOT w5.25: MC7.35@1397.63,2031.02 1438.17,2071.56 1510.62,2071.56 1544.34,2105.29 1563.24,2105.29 1839.52,2381.56 1839.52,2944.92 1970.72,3076.12 3014.65,3076.12 3247.69,2843.08 3596.61,2843.08 3602.3,2837.39 v1(3606.29,2837.39)
B67_L18N: MC3.67 MC7.26 | length 2393
  L1-Top w5.25: MC7.26@1476.37,2424.72 1476.37,2394.05 1479.45,2390.98 1519.68,2390.98 1527.98,2390.98 1777.69,2640.69 1777.69,3010.36 1889.19,3121.87 2793.76,3121.87 3000.56,2915.07 3201.71,2915.07 3202.64,2916.01 3227.42,2916.01 MC3.67@3230.7,2919.29
B67_L18P: MC3.65 MC7.28 | length 2393
  L1-Top w5.25: MC7.28@1476.37,2345.98 1476.37,2376.65 1479.45,2379.73 1519.68,2379.73 1532.64,2379.73 1788.94,2636.03 1788.94,3005.7 1893.85,3110.62 2789.1,3110.62 2995.9,2903.82 3201.71,2903.82 3202.64,2902.89 3227.42,2902.89 MC3.65@3230.7,2899.6
B67_L19N: MC3.76 MC7.21 | length 2740
  L1-Top w5.25: MC3.76@3474.01,3037.4 3477.29,3034.12 3502.06,3034.12 3503,3033.18 3512.13,3033.18 3532.85,3033.18 3540.22,3040.56 v1(3543.3,3040.56)
  L4-BOT w5.25: MC7.21@1397.63,2582.2 1438.73,2623.3 1510.07,2623.3 1544.4,2588.98 1558.58,2588.98 1724.77,2755.17 1724.77,2807.17 1724.77,2992.45 1923.19,3190.87 3079.11,3190.87 3275.78,2994.2 3415.29,2994.2 3454.27,3033.18 3532.85,3033.18 3540.22,3040.56 v1(3543.3,3040.56)
B67_L19P: MC3.74 MC7.23 | length 2739.5
  L1-Top w5.25: MC3.74@3474.01,3017.72 3477.29,3021 3502.06,3021 3503,3021.93 3516.79,3021.93 3532.85,3021.93 3540.22,3014.56 v1(3543.3,3014.56)
  L4-BOT w5.25: MC7.23@1397.63,2503.46 1438.17,2544 1510.62,2544 1544.34,2577.73 1563.24,2577.73 1736.02,2750.51 1736.02,2987.79 1927.85,3179.62 3074.45,3179.62 3271.12,2982.95 3419.95,2982.95 3458.93,3021.93 3532.85,3021.93 3540.22,3014.56 v1(3543.3,3014.56)
B67_L20N: MC3.39 MC7.38 | length 3613.2
  L1-Top w5.25: MC7.38@1476.37,1952.28 1476.37,1921.61 1479.45,1918.54 1604.56,1918.54 1783.26,1739.84 1783.26,981.79 1829.39,935.67 2424.21,935.67 2719.26,1230.72 2719.26,1925.3 3098.79,2304.84 3201.71,2304.84 3202.64,2305.77 3227.42,2305.77 MC3.39@3230.7,2309.05
B67_L20P: MC3.37 MC7.40 | length 3613.2
  L1-Top w5.25: MC7.40@1476.37,1873.54 1476.37,1904.21 1479.45,1907.29 1599.91,1907.29 1772.01,1735.18 1772.01,977.13 1824.73,924.42 2428.87,924.42 2730.51,1226.06 2730.51,1920.65 3103.45,2293.59 3201.71,2293.59 3202.64,2292.65 3227.42,2292.65 MC3.37@3230.7,2289.37
B67_L21N: MC3.75 MC7.18 | length 2159.9
  L1-Top w5.25: MC7.18@1476.37,2739.68 1476.37,2709.01 1479.45,2705.94 1519.68,2705.94 1528.25,2705.94 1691.5,2869.19 1691.5,3049.56 1832.81,3190.87 2867.54,3190.87 3025.23,3033.18 3194.28,3033.18 3201.71,3033.18 3202.64,3034.12 3227.42,3034.12 MC3.75@3230.7,3037.4
B67_L21P: MC3.73 MC7.20 | length 2159.9
  L1-Top w5.25: MC7.20@1476.37,2660.94 1476.37,2691.61 1479.45,2694.69 1519.68,2694.69 1532.91,2694.69 1702.75,2864.53 1702.75,3044.9 1837.47,3179.62 2862.88,3179.62 3020.57,3021.93 3189.62,3021.93 3201.71,3021.93 3202.64,3021 3227.42,3021 MC3.73@3230.7,3017.72
B67_L22N: MC3.63 MC7.30 | length 2509.2
  L1-Top w5.25: MC7.30@1476.37,2267.24 1476.37,2236.57 1479.45,2233.5 1519.68,2233.5 1532.22,2233.5 1816.8,2518.08 1816.8,2981.84 1922.32,3087.37 2761.22,3087.37 2992.58,2856.02 3201.71,2856.02 3202.64,2856.95 3227.42,2856.95 MC3.63@3230.7,2860.23
B67_L22P: MC3.61 MC7.32 | length 2509.2
  L1-Top w5.25: MC7.32@1476.37,2188.5 1476.37,2219.17 1479.45,2222.25 1519.68,2222.25 1536.88,2222.25 1828.05,2513.42 1828.05,2977.18 1926.98,3076.12 2756.56,3076.12 2987.92,2844.77 3201.71,2844.77 3202.64,2843.83 3227.42,2843.83 MC3.61@3230.7,2840.55
B67_L23N: MC3.79 MC7.14 | length 2045
  L1-Top w5.25: MC7.14@1476.37,2897.16 1476.37,2866.49 1479.45,2863.42 1519.68,2863.42 1641.99,2985.73 1641.99,3072.02 1797.03,3227.06 2891.28,3227.06 3026.1,3092.24 3201.71,3092.24 3202.64,3093.17 3227.42,3093.17 MC3.79@3230.7,3096.46
B67_L23P: MC3.77 MC7.16 | length 2045
  L1-Top w5.25: MC7.16@1476.37,2818.42 1476.37,2849.09 1479.45,2852.17 1524.34,2852.17 1653.24,2981.07 1653.24,3067.36 1801.69,3215.81 2886.62,3215.81 3021.44,3080.99 3201.71,3080.99 3202.64,3080.05 3227.42,3080.05 MC3.77@3230.7,3076.77
B67_L24N: MC3.72 MC7.25 | length 2970.4
  L1-Top w5.25: MC3.72@3474.01,2978.35 3477.29,2975.06 3502.06,2975.06 3503,2974.13 3595.84,2974.13 3603.22,2981.5 v1(3606.29,2981.5)
  L4-BOT w5.25: MC7.25@1397.63,2424.72 1438.73,2465.82 1510.07,2465.82 1544.4,2431.5 1558.58,2431.5 1759.27,2632.19 1759.27,2760.14 1759.27,2811.83 1759.27,2978.16 1937.48,3156.37 3064.82,3156.37 3261.49,2959.7 3439.84,2959.7 3454.27,2974.13 3595.84,2974.13 3603.22,2981.5 v1(3606.29,2981.5)
B67_L24P: MC3.70 MC7.27 | length 2969.9
  L1-Top w5.25: MC3.70@3474.01,2958.66 3477.29,2961.94 3502.06,2961.94 3503,2962.88 3595.84,2962.88 3603.22,2955.5 v1(3606.29,2955.5)
  L4-BOT w5.25: MC7.27@1397.63,2345.98 1438.17,2386.52 1510.62,2386.52 1544.34,2420.25 1563.24,2420.25 1770.52,2627.53 1770.52,2764.8 1770.52,2973.5 1942.14,3145.12 3060.16,3145.12 3256.83,2948.45 3444.5,2948.45 3458.93,2962.88 3595.84,2962.88 3603.22,2955.5 v1(3606.29,2955.5)
B67_T3U_N12: MC3.78 MC7.19 R7.2 | length 2764.4
  L1-Top w7.5: R7.2@1131.89,2660.94 1131.89,2662.91 1145.86,2676.88 1147.82,2676.88 1170.65,2699.7 1358.87,2699.7 MC7.19@1397.63,2660.94 ; v1(3415.64,3076.77) MC3.78@3474.01,3076.77
  L4-BOT w7.5: MC7.19@1397.63,2660.94 1437.14,2700.45 1539.03,2700.45 1692.91,2854.33 1692.91,3011.81 1908.16,3227.06 3137.53,3227.06 3287.82,3076.77 v1(3415.64,3076.77)
B84_L1N: MC1.64 MC5.23 | length 3459.8
  L1-Top w5.25: MC1.64@3954.72,1416.73 3954.72,1436.22 3961.15,1442.65 3961.76,1442.65 3964.84,1445.73 3964.84,1547.69 5420.82,3003.67 5428.78,3011.62 5535.51,3118.36 5535.51,3946.77 5565.23,3976.49 5565.23,4174.09 5562.16,4177.16 MC5.23@5531.49,4177.16
B84_L1P: MC1.62 MC5.25 | length 3459.8
  L1-Top w5.25: MC1.62@3986.21,1416.73 3986.21,1436.22 3979.78,1442.65 3979.16,1442.65 3976.09,1445.73 3976.09,1543.03 5428.78,2995.71 5432.75,2999.69 5546.76,3113.7 5546.76,3942.11 5576.48,3971.83 5576.48,4174.09 5579.56,4177.16 MC5.25@5610.23,4177.16
B84_L2N: MC1.71 MC5.16 | length 4332.1
  L1-Top w5.25: MC1.71@3828.73,1173.82 3828.73,1154.33 3835.16,1147.9 3835.78,1147.9 3838.86,1144.82 3838.86,1117.96 3831.48,1110.58 v1(3831.48,1107.48)
  L4-BOT w5.25: v1(3831.48,1107.48) 3831.48,1110.56 3838.86,1117.93 3838.86,1517.19 4278.1,1956.44 4818.91,1956.44 5440,2577.52 5440,3827.71 5209.75,4057.96 5209.75,4109.14 5175.43,4143.46 5175.43,4214.8 MC5.16@5216.53,4255.9
B84_L2P: MC1.69 MC5.18 | length 4331.6
  L1-Top w5.25: v1(3857.48,1107.48) 3857.48,1110.58 3850.11,1117.96 3850.11,1144.82 3853.18,1147.9 3853.8,1147.9 3860.23,1154.33 MC1.69@3860.23,1173.82
  L4-BOT w5.25: v1(3857.48,1107.48) 3857.48,1110.56 3850.11,1117.93 3850.11,1512.53 4282.76,1945.19 4823.57,1945.19 5451.25,2572.86 5451.25,3832.37 5221,4062.62 5221,4109.19 5254.73,4142.92 5254.73,4215.36 MC5.18@5295.27,4255.9
B84_L3N: MC1.72 MC5.15 | length 3560.7
  L1-Top w5.25: MC1.72@3828.73,1416.73 3828.73,1436.22 3835.16,1442.65 3835.78,1442.65 3838.86,1445.73 3838.86,1519.28 5372.03,3052.46 5405.08,3085.5 5466.51,3146.94 5466.51,3816.78 5417.31,3865.98 5409.36,3873.93 5250.27,4033.02 5250.27,4174.09 5247.2,4177.16 MC5.15@5216.53,4177.16
B84_L3P: MC1.70 MC5.17 | length 3560.7
  L1-Top w5.25: MC1.70@3860.23,1416.73 3860.23,1436.22 3853.8,1442.65 3853.18,1442.65 3850.11,1445.73 3850.11,1514.62 5379.98,3044.5 5409.74,3074.25 5477.76,3142.28 5477.76,3821.44 5417.31,3881.89 5261.52,4037.68 5261.52,4174.09 5264.6,4177.16 MC5.17@5295.27,4177.16
B84_L4N: MC1.63 MC5.24 | length 4219.6
  L1-Top w5.25: MC1.63@3954.72,1173.82 3954.72,1154.33 3961.15,1147.9 3961.76,1147.9 3964.84,1144.82 3964.84,1117.96 3957.46,1110.58 v1(3957.46,1107.48)
  L4-BOT w5.25: v1(3957.46,1107.48) 3957.46,1110.56 3964.84,1117.93 3964.84,1545.6 4306.68,1887.44 4847.49,1887.44 5509,2548.94 5509,3977.1 5524.71,3992.81 5524.71,4109.14 5490.39,4143.46 5490.39,4214.8 MC5.24@5531.49,4255.9
B84_L4P: MC1.61 MC5.26 | length 4219.1
  L1-Top w5.25: v1(3983.46,1107.48) 3983.46,1110.58 3976.09,1117.96 3976.09,1144.82 3979.16,1147.9 3979.78,1147.9 3986.21,1154.33 MC1.61@3986.21,1173.82
  L4-BOT w5.25: v1(3983.46,1107.48) 3983.46,1110.56 3976.09,1117.93 3976.09,1540.94 4311.34,1876.19 4852.15,1876.19 5520.25,2544.28 5520.25,3972.44 5535.96,3988.15 5535.96,4109.19 5569.69,4142.92 5569.69,4215.36 MC5.26@5610.23,4255.9
B84_L5N_HDGC: MC1.76 MC5.11 | length 3623.4
  L1-Top w5.25: MC1.76@3765.74,1416.73 3765.74,1436.22 3772.17,1442.65 3772.79,1442.65 3775.86,1445.73 3775.86,1505.08 5347.63,3076.85 5390.79,3120 5432.01,3161.23 5432.01,3782.11 5092.79,4121.32 5092.79,4174.09 5089.72,4177.16 MC5.11@5059.05,4177.16
B84_L5P_HDGC: MC1.74 MC5.13 | length 3623.4
  L1-Top w5.25: MC1.74@3797.24,1416.73 3797.24,1436.22 3790.81,1442.65 3790.19,1442.65 3787.11,1445.73 3787.11,1500.42 5355.59,3068.9 5395.45,3108.75 5443.26,3156.57 5443.26,3786.77 5104.04,4125.98 5104.04,4174.09 5107.12,4177.16 MC5.13@5137.79,4177.16
B84_L6N_HDGC: MC1.67 MC5.20 | length 4136.6
  L1-Top w5.25: MC1.67@3891.72,1173.82 3891.72,1193.31 3898.15,1199.74 3898.77,1199.74 3901.85,1202.81 3901.85,1229.68 3894.47,1237.05 v1(3894.47,1240.16)
  L4-BOT w5.25: v1(3894.47,1240.16) 3894.47,1243.23 3901.85,1250.61 3901.85,1531.4 4292.39,1921.94 4833.2,1921.94 5474.5,2563.23 5474.5,3918.77 5367.23,4026.04 5367.23,4109.14 5332.91,4143.46 5332.91,4214.8 MC5.20@5374.01,4255.9
B84_L6P_HDGC: MC1.65 MC5.22 | length 4136.2
  L1-Top w5.25: v1(3920.47,1240.16) 3920.47,1237.05 3913.1,1229.68 3913.1,1202.81 3916.17,1199.74 3916.79,1199.74 3923.22,1193.31 MC1.65@3923.22,1173.82
  L4-BOT w5.25: v1(3920.47,1240.16) 3920.47,1243.23 3913.1,1250.61 3913.1,1526.74 4297.05,1910.69 4837.86,1910.69 5485.75,2558.57 5485.75,3923.43 5378.48,4030.7 5378.48,4109.19 5412.21,4142.92 5412.21,4215.36 MC5.22@5452.75,4255.9
B84_L7N_HDGC: MC2.62 MC5.8 | length 2529.2
  L1-Top w5.25: MC2.62@3986.21,3700.2 3986.21,3680.71 3992.64,3674.28 3993.26,3674.28 3996.34,3671.2 3996.34,3650.93 4024.73,3622.53 4829.36,3622.53 4846.51,3639.68 4985.44,3639.68 5035.04,3689.27 5035.04,3748.03 5035.04,3835.86 4919.44,3951.47 4751.62,3951.47 4649.27,4053.82 4573.45,4129.64 4573.45,4303.35 4623.5,4353.4 4903.91,4353.4 4935.31,4321.99 4935.31,4258.98 4932.24,4255.9 MC5.8@4901.57,4255.9
B84_L7P_HDGC: MC2.60 MC5.10 | length 2529.2
  L1-Top w5.25: MC2.60@4017.71,3700.2 4017.71,3680.71 4011.28,3674.28 4010.66,3674.28 4007.59,3671.2 4007.59,3655.59 4029.39,3633.78 4824.7,3633.78 4841.85,3650.93 4980.78,3650.93 5023.79,3693.93 5023.79,3748.03 5023.79,3831.2 4914.78,3940.22 4746.96,3940.22 4565.49,4121.69 4562.2,4124.98 4562.2,4308.01 4618.84,4364.65 4908.57,4364.65 4946.56,4326.65 4946.56,4258.98 4949.64,4255.9 MC5.10@4980.31,4255.9
B84_L8N_HDGC: MC1.75 MC5.12 | length 4262.1
  L1-Top w5.25: MC1.75@3765.74,1173.82 3765.74,1193.31 3772.17,1199.74 3772.79,1199.74 3775.86,1202.81 3775.86,1229.68 3768.49,1237.05 v1(3768.49,1240.16)
  L4-BOT w5.25: v1(3768.49,1240.16) 3768.49,1243.23 3775.86,1250.61 3775.86,1502.99 4263.81,1990.94 4804.62,1990.94 5405.5,2591.81 5405.5,3728.19 5052.27,4081.42 5052.27,4109.14 5017.95,4143.46 5017.95,4214.8 MC5.12@5059.05,4255.9
B84_L8P_HDGC: MC1.73 MC5.14 | length 4261.6
  L1-Top w5.25: v1(3794.49,1240.16) 3794.49,1237.05 3787.11,1229.68 3787.11,1202.81 3790.19,1199.74 3790.81,1199.74 3797.24,1193.31 MC1.73@3797.24,1173.82
  L4-BOT w5.25: v1(3794.49,1240.16) 3794.49,1243.23 3787.11,1250.61 3787.11,1498.33 4268.47,1979.69 4809.28,1979.69 5416.75,2587.15 5416.75,3732.85 5063.52,4086.08 5063.52,4109.19 5097.25,4142.92 5097.25,4215.36 MC5.14@5137.79,4255.9
B84_L9N: MC1.68 MC5.19 | length 3498
  L1-Top w5.25: MC1.68@3891.72,1416.73 3891.72,1436.22 3898.15,1442.65 3898.77,1442.65 3901.85,1445.73 3901.85,1533.48 5396.43,3028.06 5419.37,3051 5501.01,3132.65 5501.01,3864.27 5488.18,3877.1 5480.23,3885.05 5407.75,3957.53 5407.75,4174.09 5404.68,4177.16 MC5.19@5374.01,4177.16
B84_L9P: MC1.66 MC5.21 | length 3498
  L1-Top w5.25: MC1.66@3923.22,1416.73 3923.22,1436.22 3916.79,1442.65 3916.17,1442.65 3913.1,1445.73 3913.1,1528.82 5404.38,3020.11 5424.03,3039.75 5512.26,3127.99 5512.26,3868.93 5488.18,3893.01 5419,3962.19 5419,4174.09 5422.08,4177.16 MC5.21@5452.75,4177.16
B84_L10N: MC2.61 MC5.7 | length 1919.2
  L1-Top w5.25: MC2.61@3986.21,3457.28 3986.21,3476.77 3992.64,3483.2 3993.26,3483.2 3996.34,3486.28 3996.34,3498.36 4040.34,3542.36 4877.99,3542.36 4895.26,3559.62 5040.04,3559.62 5047.24,3566.82 5174.79,3694.38 5174.79,3888.9 4935.31,4128.38 4935.31,4174.09 4932.24,4177.16 MC5.7@4901.57,4177.16
B84_L10P: MC2.59 MC5.9 | length 1919.2
  L1-Top w5.25: MC2.59@4017.71,3457.28 4017.71,3476.77 4011.28,3483.2 4010.66,3483.2 4007.59,3486.28 4007.59,3493.7 4045,3531.11 4882.65,3531.11 4899.92,3548.37 5044.7,3548.37 5047.24,3550.91 5186.04,3689.72 5186.04,3893.56 4946.56,4133.04 4946.56,4174.09 4949.64,4177.16 MC5.9@4980.31,4177.16
B84_L11N: MC2.66 MC5.4 | length 2450.3
  L1-Top w5.25: MC2.66@3923.22,3700.2 3923.22,3680.71 3929.65,3674.28 3930.27,3674.28 3933.34,3671.2 3933.34,3631.18 3972.89,3591.63 4846.53,3591.63 4864.02,3609.13 5003.69,3609.13 5047.24,3652.68 5079.24,3684.68 5079.24,3851.97 4926.17,4005.04 4746.84,4005.04 4673.66,4078.22 4607.95,4143.93 4607.95,4289.06 4637.79,4318.9 4767.71,4318.9 4777.83,4308.77 4777.83,4258.98 4774.76,4255.9 MC5.4@4744.09,4255.9
B84_L11P: MC2.64 MC5.6 | length 2450.3
  L1-Top w5.25: MC2.64@3954.72,3700.2 3954.72,3680.71 3948.29,3674.28 3947.67,3674.28 3944.59,3671.2 3944.59,3635.84 3977.55,3602.88 4841.87,3602.88 4859.36,3620.38 4999.03,3620.38 5047.24,3668.59 5067.99,3689.34 5067.99,3847.31 4921.51,3993.79 4742.18,3993.79 4599.99,4135.98 4596.7,4139.27 4596.7,4293.72 4633.13,4330.15 4772.37,4330.15 4789.08,4313.43 4789.08,4258.98 4792.16,4255.9 MC5.6@4822.83,4255.9
B84_L12N: MC2.65 MC5.3 | length 2034
  L1-Top w5.25: MC2.65@3923.22,3457.28 3923.22,3476.77 3929.65,3483.2 3930.27,3483.2 3933.34,3486.28 3933.34,3504 4000.25,3570.91 4856.74,3570.91 4875.47,3589.64 5017.07,3589.64 5047.24,3619.8 5119.69,3692.25 5119.69,3868.12 4945.24,4042.57 4842.9,4042.57 4777.83,4107.64 4777.83,4174.09 4774.76,4177.16 MC5.3@4744.09,4177.16
B84_L12P: MC2.63 MC5.5 | length 2034
  L1-Top w5.25: MC2.63@3954.72,3457.28 3954.72,3476.77 3948.29,3483.2 3947.67,3483.2 3944.59,3486.28 3944.59,3499.34 4004.91,3559.66 4861.4,3559.66 4880.13,3578.39 5021.73,3578.39 5047.24,3603.89 5130.94,3687.59 5130.94,3872.78 4949.9,4053.82 4847.56,4053.82 4789.08,4112.3 4789.08,4174.09 4792.16,4177.16 MC5.5@4822.83,4177.16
